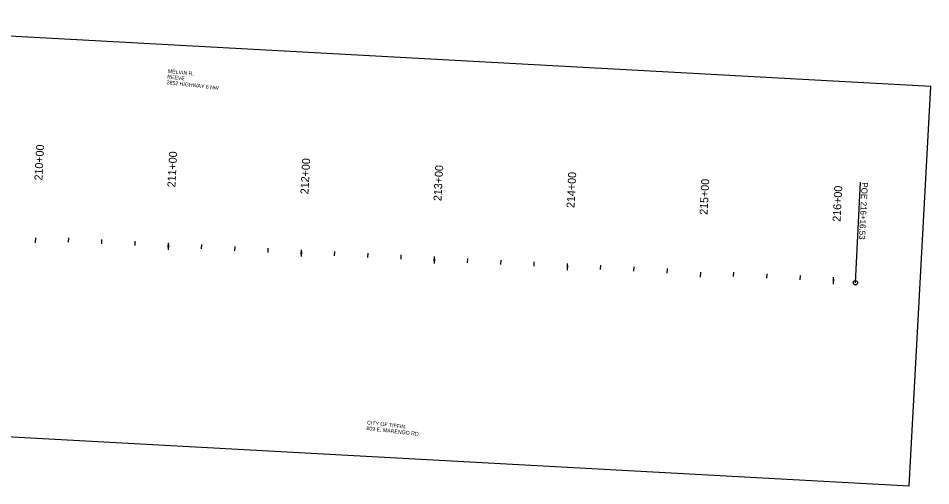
# Model space of a CAD drawing. Extents: x 20499788 to 20505371, y 7953467 to 7954209.
# Drawn here: x 20504686 to 20505371, y 7953467 to 7953817 of the extents above; entities that cross this region are included whole.
import ezdxf

# ---------------------------------------------------------------- set-up
doc = ezdxf.new("R2010")
doc.units = 0
for name, color, linetype in [('NamedBoundary', 7, 'Continuous'), ('Text', 7, 'Continuous'), ('TextAlignment', 7, 'Continuous'), ('TextAlignmentLrg', 7, 'Continuous'), ('TextAlignmentSml', 7, 'Continuous')]:
    doc.layers.add(name, color=color, linetype=linetype)

msp = doc.modelspace()

# ---------------------------------------------------------------- linework, layer by layer
at = {"layer": 'NamedBoundary'}
msp.add_lwpolyline([(20504431.55, 7953817.36), (20504415.22, 7953517.81), (20505354.3, 7953466.63), (20505370.62, 7953766.18)], close=True, dxfattribs=at)
at = {"layer": 'TextAlignment'}
for p in [(20505314.06, 7953618.94), (20505317.95, 7953694.44)]:
    msp.add_line(p, (20505317.95, 7953694.44), dxfattribs=at)
msp.add_circle((20505314.06, 7953618.94), 1.6, dxfattribs=at)
at = {"layer": 'TextAlignmentLrg'}
for p, q in [((20504698.44, 7953652.52), (20504698.25, 7953648.85)), ((20504798.21, 7953645.53), (20504798.38, 7953648.8)), ((20504898.08, 7953640.38), (20504898.25, 7953643.66)), ((20504997.95, 7953635.24), (20504998.12, 7953638.51)), ((20505097.82, 7953630.09), (20505097.98, 7953633.36)), ((20505197.78, 7953626.77), (20505197.59, 7953623.1)), ((20505297.55, 7953619.79), (20505297.72, 7953623.06))]:
    msp.add_line(p, q, dxfattribs=at)
at = {"layer": 'TextAlignmentSml'}
for p, q in [((20504698.44, 7953652.52), (20504698.25, 7953648.85)), ((20504723.31, 7953649.39), (20504723.48, 7953652.67)), ((20504748.28, 7953648.11), (20504748.45, 7953651.38)), ((20504773.25, 7953646.82), (20504773.42, 7953650.09)), ((20504798.31, 7953647.37), (20504798.12, 7953643.7)), ((20504823.18, 7953644.25), (20504823.35, 7953647.52)), ((20504848.15, 7953642.96), (20504848.32, 7953646.23)), ((20504873.11, 7953641.67), (20504873.28, 7953644.94)), ((20504898.18, 7953642.22), (20504897.99, 7953638.55)), ((20504923.05, 7953639.1), (20504923.22, 7953642.37)), ((20504948.01, 7953637.81), (20504948.18, 7953641.08)), ((20504972.98, 7953636.52), (20504973.15, 7953639.79)), ((20504998.04, 7953637.07), (20504997.85, 7953633.4)), ((20505022.91, 7953633.95), (20505023.08, 7953637.22)), ((20505047.88, 7953632.66), (20505048.05, 7953635.93)), ((20505072.85, 7953631.37), (20505073.02, 7953634.65)), ((20505097.91, 7953631.92), (20505097.72, 7953628.25)), ((20505122.78, 7953628.8), (20505122.95, 7953632.07)), ((20505147.75, 7953627.51), (20505147.92, 7953630.78)), ((20505172.72, 7953626.23), (20505172.88, 7953629.5)), ((20505197.78, 7953626.77), (20505197.59, 7953623.1)), ((20505222.65, 7953623.65), (20505222.82, 7953626.92)), ((20505247.62, 7953622.36), (20505247.79, 7953625.64)), ((20505272.58, 7953621.08), (20505272.75, 7953624.35)), ((20505297.64, 7953621.62), (20505297.46, 7953617.96))]:
    msp.add_line(p, q, dxfattribs=at)

# ---------------------------------------------------------------- texts
at = {"layer": 'Text'}
for s, height, rotation, p in [('REEVE', 2.835, 353.65909, (20504797.33, 7953772.21)), ('MELVIN R. ', 2.835, 353.65909, (20504797.8, 7953776.43)), ('2852 HIGHWAY 6 NW', 2.8346, 353.65909, (20504796.86, 7953767.98)), ('CITY OF TIFFIN', 2.8346, 353.49015, (20504947.38, 7953512.72)), ('809 E. MARENGO RD.', 2.8346, 353.49015, (20504946.9, 7953508.5))]:
    msp.add_text(s, height=height, rotation=rotation, dxfattribs=at).set_placement(p)
at = {"layer": 'TextAlignment'}
for s, p in [('POE ', (20505318.94, 7953694.39)), ('216+16.53', (20505318.2, 7953679.96))]:
    msp.add_text(s, height=4.5, rotation=267.04866, dxfattribs=at).set_placement(p)
at = {"layer": 'TextAlignmentLrg'}
for s, p in [('210+00', (20504703.67, 7953695.47)), ('215+00', (20505203, 7953669.72))]:
    msp.add_text(s, height=6.012, rotation=87.04866, dxfattribs=at).set_placement(p)
at = {"layer": 'TextAlignmentSml'}
for s, p in [('210+00', (20504703.67, 7953695.47)), ('211+00', (20504803.53, 7953690.32)), ('212+00', (20504903.4, 7953685.17)), ('213+00', (20505003.27, 7953680.02)), ('214+00', (20505103.13, 7953674.87)), ('215+00', (20505203, 7953669.72)), ('216+00', (20505302.87, 7953664.57))]:
    msp.add_text(s, height=6.012, rotation=87.04866, dxfattribs=at).set_placement(p)

doc.saveas('drawing.dxf')
